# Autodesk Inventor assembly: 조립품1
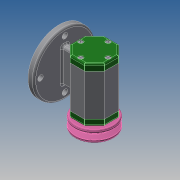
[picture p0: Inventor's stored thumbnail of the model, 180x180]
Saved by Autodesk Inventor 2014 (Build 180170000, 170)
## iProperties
Created: 2021-02
Part Number: 조립품1
Document SubType Name: Assembly
Designer: kb542-14
Author: kb542-14
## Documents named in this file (13)
- C:\Users\kb542-14\Desktop\조립품1.iam
- C:\Users\kb542-14\Desktop\본체.ipt
- C:\Users\kb542-14\Desktop\710204V1019\V벨트풀리.ipt
- C:\Users\kb542-14\Desktop\710204V1019\너트 M8.ipt
- C:\Users\kb542-14\Desktop\710204V1019\뒤커버.ipt
- C:\Users\kb542-14\Desktop\710204V1019\베어링 15 x 32 x 9.ipt
- C:\Users\kb542-14\Desktop\710204V1019\볼트 M4 x 12.ipt
- C:\Users\kb542-14\Desktop\710204V1019\스프링와셔 8.ipt
- C:\Users\kb542-14\Desktop\710204V1019\앞커버.ipt
- C:\Users\kb542-14\Desktop\710204V1019\오일 실 15 25 7.ipt
- C:\Users\kb542-14\Desktop\710204V1019\와셔 8x17.ipt
- C:\Users\kb542-14\Desktop\710204V1019\축.ipt
- C:\Users\kb542-14\Desktop\710204V1019\키 3 x 3 x 12.ipt
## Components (1 placed, 1 different names)
1. V벨트풀리:1
